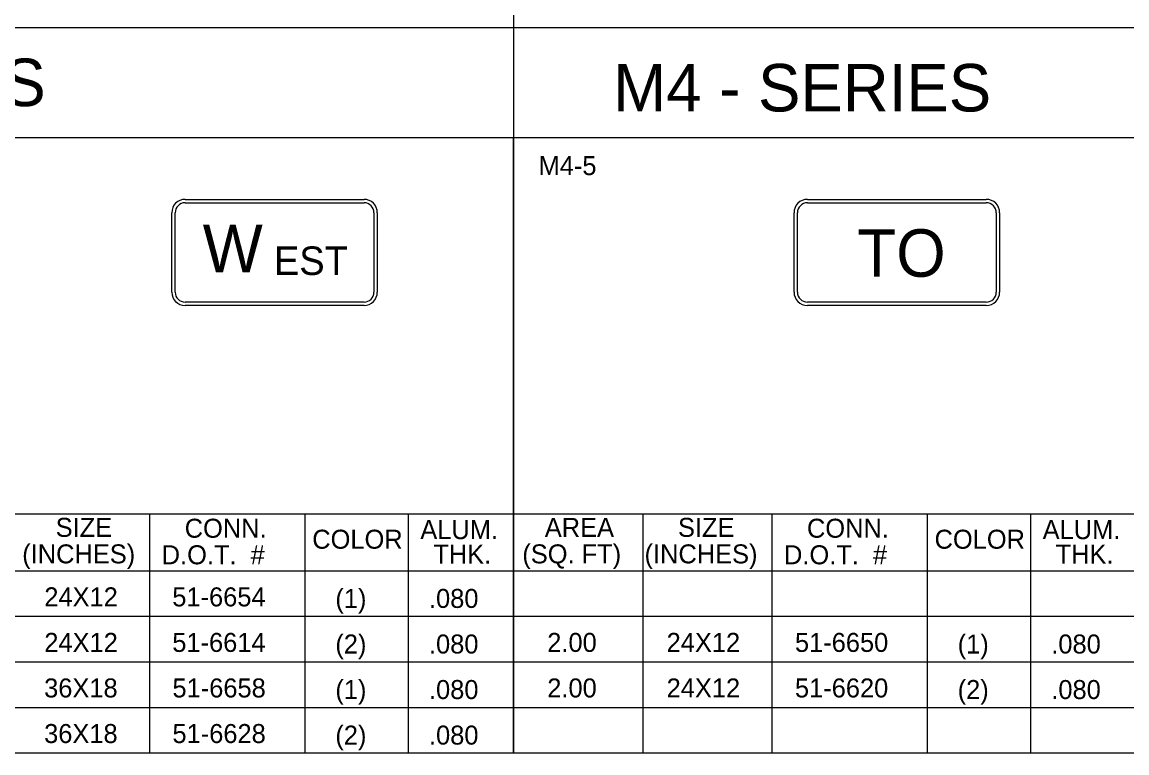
# Model space of a CAD drawing. Extents: x 0 to 2011, y -22 to 1183.
# Drawn here: x 341.3 to 527.3, y 269.1 to 392.2 of the extents above; entities that cross this region are included whole.
import ezdxf

# ---------------------------------------------------------------- set-up
doc = ezdxf.new("R2010")
doc.units = 0
for name, color, linetype in [('Default', 7, 'Continuous'), ('Level 1', 7, 'Continuous'), ('Level 2', 7, 'Continuous'), ('Level 5', 7, 'Continuous')]:
    doc.layers.add(name, color=color, linetype=linetype)

msp = doc.modelspace()

# ---------------------------------------------------------------- linework, layer by layer
at = {"layer": 'Default'}
msp.add_line((1262.03, 391.26), (5.05, 391.26), dxfattribs=at)
at = {"layer": 'Level 1'}
for p, q in [((368.76, 362.36), (398.88, 362.36)), ((368.76, 361.79), (398.88, 361.79)), ((473.51, 362.36), (503.63, 362.36)), ((473.51, 361.79), (503.63, 361.79)), ((366.52, 346.73), (366.52, 360.12)), ((367.09, 346.73), (367.09, 360.12)), ((400.55, 360.12), (400.55, 346.73)), ((401.12, 360.12), (401.12, 346.73)), ((471.27, 346.73), (471.27, 360.12)), ((471.84, 346.73), (471.84, 360.12)), ((505.3, 360.12), (505.3, 346.73)), ((505.87, 360.12), (505.87, 346.73)), ((398.88, 345.06), (368.76, 345.06)), ((398.88, 344.49), (368.76, 344.49)), ((503.63, 345.06), (473.51, 345.06)), ((503.63, 344.49), (473.51, 344.49))]:
    msp.add_line(p, q, dxfattribs=at)
for centre, radius, start, end in [((368.76, 360.12), 2.24, 90, 180.0015), ((368.76, 360.12), 1.67, 90, 180), ((398.88, 360.12), 2.24, 359.9993, 90), ((398.88, 360.12), 1.67, 0, 90), ((473.51, 360.12), 2.24, 90, 180.0015), ((473.51, 360.12), 1.67, 90, 180), ((503.63, 360.12), 2.24, 359.9993, 90), ((503.63, 360.12), 1.67, 0, 90), ((368.76, 346.73), 2.24, 179.998, 270), ((368.76, 346.73), 1.67, 180, 270), ((398.88, 346.73), 1.67, 270, 360), ((398.88, 346.73), 2.24, 270, 0.0005), ((473.51, 346.73), 2.24, 179.998, 270), ((473.51, 346.73), 1.67, 180, 270), ((503.63, 346.73), 1.67, 270, 360), ((503.63, 346.73), 2.24, 270, 0.0005)]:
    msp.add_arc(centre, radius, start, end, dxfattribs=at)
at = {"layer": 'Level 2'}
for p, q in [((319.3, 309.4), (424.05, 309.4)), ((362.8, 309.4), (362.8, 269.13)), ((388.9, 309.4), (388.9, 269.13)), ((406.3, 309.4), (406.3, 269.13)), ((424.05, 309.4), (528.79, 309.4)), ((445.8, 309.4), (445.8, 269.13)), ((467.55, 309.4), (467.55, 269.13)), ((493.65, 309.4), (493.65, 269.13)), ((511.05, 309.4), (511.05, 269.13)), ((319.3, 299.81), (424.05, 299.81)), ((424.05, 299.81), (528.79, 299.81)), ((319.3, 292.14), (424.05, 292.14)), ((424.05, 292.14), (528.79, 292.14)), ((319.3, 284.47), (424.05, 284.47)), ((424.05, 284.47), (528.79, 284.47)), ((319.3, 276.8), (424.05, 276.8)), ((424.05, 276.8), (528.79, 276.8))]:
    msp.add_line(p, q, dxfattribs=at)
for points in [[(424.05, 372.75), (319.3, 372.75), (319.3, 269.13), (424.05, 269.13)], [(528.79, 372.75), (424.05, 372.75), (424.05, 269.13), (528.79, 269.13)]]:
    msp.add_lwpolyline(points, close=True, dxfattribs=at)
at = {"layer": 'Level 5'}
for p, q in [((424.05, 830), (424.05, 391.26)), ((424.05, 391.26), (424.05, 269.13))]:
    msp.add_line(p, q, dxfattribs=at)

# ---------------------------------------------------------------- texts
at = {"layer": 'Level 1'}
for s, p in [('M3 - SERIES', (281.7, 378.07)), ('M4 - SERIES', (440.84, 377.17)), ('W', (371.74, 350.09))]:
    msp.add_text(s, height=8, dxfattribs=at).set_placement(p)
at = {"layer": 'Level 2'}
for s, height, p in [('M4-5', 3.2, (428.26, 366.45)), ('TO', 8, (481.93, 349.33)), ('EST', 4.8, (383.7, 349.63)), ('SIZE', 3.2, (346.98, 305.52)), ('AREA', 3.2, (429.31, 305.52)), ('SIZE', 3.2, (451.73, 305.52)), ('CONN.', 3.2, (368.7, 305.37)), ('ALUM.', 3.2, (408.36, 305.14)), ('CONN.', 3.2, (473.44, 305.37)), ('ALUM.', 3.2, (513.11, 305.14)), ('COLOR', 3.2, (390.17, 303.52)), ('COLOR', 3.2, (494.92, 303.52)), ('(INCHES)', 3.2, (341.35, 301.05)), ('D.O.T.  #', 3.2, (364.83, 300.9)), ('THK.', 3.2, (410.54, 301)), ('(SQ. FT)', 3.2, (425.53, 301.05)), ('(INCHES)', 3.2, (446.1, 301.05)), ('D.O.T.  #', 3.2, (469.58, 300.9)), ('THK.', 3.2, (515.29, 301))]:
    msp.add_text(s, height=height, dxfattribs=at).set_placement(p)
at = {"layer": 'Level 5'}
for s, p in [('24X12', (345.07, 293.81)), ('51-6654', (366.61, 293.81)), ('(1)', (394.06, 293.55)), ('.080', (409.82, 293.55)), ('24X12', (345.07, 286.14)), ('51-6614', (366.61, 286.14)), ('(2)', (394.06, 285.87)), ('.080', (409.82, 285.87)), (' 2.00', (428.54, 286.14)), ('24X12', (449.82, 286.14)), ('51-6650', (471.42, 286.14)), ('(1)', (498.81, 285.87)), ('.080', (514.57, 285.87)), ('36X18', (345.04, 278.47)), ('51-6658', (366.64, 278.47)), ('(1)', (394.06, 278.2)), ('.080', (409.82, 278.2)), (' 2.00', (428.54, 278.47)), ('24X12', (449.82, 278.47)), ('51-6620', (471.42, 278.47)), ('(2)', (498.81, 278.2)), ('.080', (514.57, 278.2)), ('36X18', (345.04, 270.79)), ('51-6628', (366.64, 270.79)), ('(2)', (394.06, 270.53)), ('.080', (409.82, 270.53))]:
    msp.add_text(s, height=3.2, dxfattribs=at).set_placement(p)

doc.saveas('drawing.dxf')
